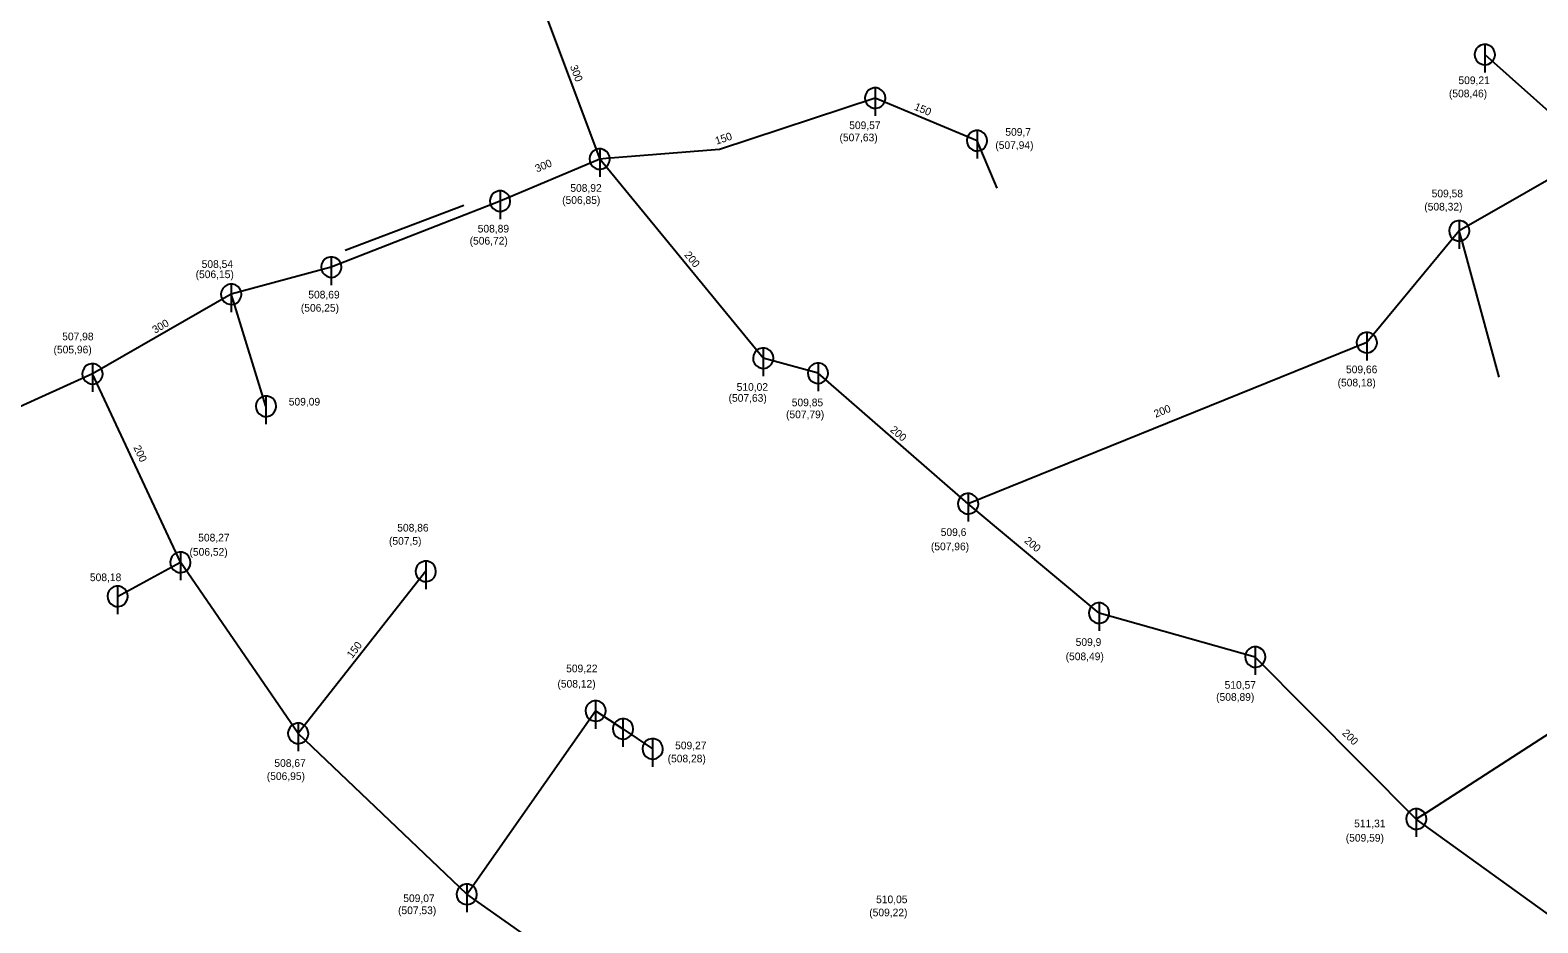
# Model space of a CAD drawing. Extents: x -476058 to -471893, y -1155786 to -1152000.
# Drawn here: x -475206.1 to -475058.6, y -1154304.2 to -1154216.9 of the extents above; entities that cross this region are included whole.
import ezdxf

# ---------------------------------------------------------------- set-up
doc = ezdxf.new("R2010")
doc.units = 0
for name, color, linetype in [('Vrstva 10', 7, 'Continuous'), ('Vrstva 18', 7, 'Continuous'), ('Vrstva 19', 7, 'Continuous'), ('Vrstva 23', 7, 'Continuous'), ('Vrstva 3', 7, 'Continuous'), ('Vrstva 4', 7, 'Continuous'), ('Vrstva 45', 7, 'Continuous'), ('Vrstva 50', 7, 'Continuous'), ('Vrstva 51', 7, 'Continuous')]:
    doc.layers.add(name, color=color, linetype=linetype)

msp = doc.modelspace()

# ---------------------------------------------------------------- linework, layer by layer
at = {"layer": 'Vrstva 10'}
for p, q in [((-475063.81, -1154218.28), (-475063.81, -1154221.03)), ((-475123.44, -1154222.53), (-475123.44, -1154225.28)), ((-475113.48, -1154226.71), (-475113.48, -1154229.46)), ((-475150.39, -1154228.5), (-475150.39, -1154231.25)), ((-475160.13, -1154232.61), (-475160.13, -1154235.36)), ((-475066.31, -1154235.52), (-475066.31, -1154238.27)), ((-475176.64, -1154239.07), (-475176.64, -1154241.82)), ((-475186.43, -1154241.72), (-475186.43, -1154244.47)), ((-475075.35, -1154246.44), (-475075.35, -1154249.19)), ((-475134.39, -1154247.97), (-475134.39, -1154250.72)), ((-475200, -1154249.5), (-475200, -1154252.25)), ((-475129.03, -1154249.44), (-475129.03, -1154252.19)), ((-475183.03, -1154252.67), (-475183.03, -1154255.42)), ((-475114.35, -1154262.2), (-475114.35, -1154264.95)), ((-475191.4, -1154267.93), (-475191.4, -1154270.68)), ((-475167.4, -1154268.81), (-475167.4, -1154271.56)), ((-475197.54, -1154271.26), (-475197.54, -1154274.01)), ((-475101.54, -1154272.89), (-475101.54, -1154275.64)), ((-475086.26, -1154277.19), (-475086.26, -1154279.94)), ((-475150.79, -1154282.46), (-475150.79, -1154285.21)), ((-475148.11, -1154284.22), (-475148.11, -1154286.96)), ((-475179.88, -1154284.66), (-475179.88, -1154287.41)), ((-475145.21, -1154286.17), (-475145.21, -1154288.92)), ((-475070.51, -1154293.03), (-475070.51, -1154295.78)), ((-475163.39, -1154300.39), (-475163.39, -1154303.14))]:
    msp.add_line(p, q, dxfattribs=at)
for points in [[(-475062.81, -1154219.28), (-475062.85, -1154219), (-475062.97, -1154218.74), (-475063.15, -1154218.53), (-475063.39, -1154218.38), (-475063.66, -1154218.29), (-475063.94, -1154218.29), (-475064.21, -1154218.36), (-475064.45, -1154218.51), (-475064.64, -1154218.72), (-475064.76, -1154218.97), (-475064.81, -1154219.25), (-475064.78, -1154219.53), (-475064.67, -1154219.79), (-475064.49, -1154220.01), (-475064.26, -1154220.17), (-475063.99, -1154220.26), (-475063.71, -1154220.28), (-475063.44, -1154220.21), (-475063.19, -1154220.07), (-475063, -1154219.86), (-475062.87, -1154219.61), (-475062.81, -1154219.34), (-475062.81, -1154219.28)], [(-475122.44, -1154223.53), (-475122.48, -1154223.25), (-475122.59, -1154223), (-475122.78, -1154222.78), (-475123.01, -1154222.63), (-475123.28, -1154222.54), (-475123.56, -1154222.54), (-475123.84, -1154222.62), (-475124.08, -1154222.76), (-475124.27, -1154222.97), (-475124.39, -1154223.23), (-475124.44, -1154223.51), (-475124.41, -1154223.79), (-475124.3, -1154224.05), (-475124.12, -1154224.27), (-475123.89, -1154224.43), (-475123.62, -1154224.52), (-475123.34, -1154224.53), (-475123.06, -1154224.46), (-475122.82, -1154224.32), (-475122.62, -1154224.12), (-475122.49, -1154223.87), (-475122.44, -1154223.59), (-475122.44, -1154223.53)], [(-475112.48, -1154227.71), (-475112.52, -1154227.43), (-475112.64, -1154227.17), (-475112.82, -1154226.96), (-475113.05, -1154226.8), (-475113.33, -1154226.72), (-475113.61, -1154226.72), (-475113.88, -1154226.79), (-475114.12, -1154226.94), (-475114.31, -1154227.15), (-475114.43, -1154227.4), (-475114.48, -1154227.68), (-475114.45, -1154227.96), (-475114.34, -1154228.22), (-475114.16, -1154228.44), (-475113.93, -1154228.6), (-475113.66, -1154228.69), (-475113.38, -1154228.71), (-475113.11, -1154228.64), (-475112.86, -1154228.5), (-475112.67, -1154228.29), (-475112.54, -1154228.04), (-475112.48, -1154227.77), (-475112.48, -1154227.71)], [(-475149.39, -1154229.5), (-475149.43, -1154229.22), (-475149.55, -1154228.96), (-475149.73, -1154228.75), (-475149.97, -1154228.59), (-475150.23, -1154228.51), (-475150.52, -1154228.51), (-475150.79, -1154228.58), (-475151.03, -1154228.73), (-475151.22, -1154228.94), (-475151.34, -1154229.19), (-475151.39, -1154229.47), (-475151.36, -1154229.75), (-475151.25, -1154230.01), (-475151.07, -1154230.23), (-475150.84, -1154230.39), (-475150.57, -1154230.48), (-475150.29, -1154230.5), (-475150.02, -1154230.43), (-475149.77, -1154230.29), (-475149.58, -1154230.08), (-475149.45, -1154229.83), (-475149.39, -1154229.56), (-475149.39, -1154229.5)], [(-475159.13, -1154233.61), (-475159.17, -1154233.33), (-475159.29, -1154233.07), (-475159.47, -1154232.86), (-475159.71, -1154232.71), (-475159.98, -1154232.62), (-475160.26, -1154232.62), (-475160.53, -1154232.69), (-475160.77, -1154232.84), (-475160.96, -1154233.05), (-475161.08, -1154233.3), (-475161.13, -1154233.58), (-475161.1, -1154233.86), (-475160.99, -1154234.12), (-475160.81, -1154234.34), (-475160.58, -1154234.5), (-475160.31, -1154234.59), (-475160.03, -1154234.61), (-475159.76, -1154234.54), (-475159.51, -1154234.4), (-475159.32, -1154234.19), (-475159.19, -1154233.94), (-475159.13, -1154233.67), (-475159.13, -1154233.61)], [(-475065.31, -1154236.52), (-475065.35, -1154236.24), (-475065.47, -1154235.98), (-475065.65, -1154235.77), (-475065.89, -1154235.61), (-475066.16, -1154235.53), (-475066.44, -1154235.53), (-475066.71, -1154235.6), (-475066.95, -1154235.75), (-475067.14, -1154235.96), (-475067.26, -1154236.21), (-475067.31, -1154236.49), (-475067.28, -1154236.77), (-475067.17, -1154237.03), (-475066.99, -1154237.25), (-475066.76, -1154237.41), (-475066.49, -1154237.5), (-475066.21, -1154237.52), (-475065.94, -1154237.45), (-475065.69, -1154237.31), (-475065.5, -1154237.1), (-475065.37, -1154236.85), (-475065.31, -1154236.58), (-475065.31, -1154236.52)], [(-475175.64, -1154240.07), (-475175.68, -1154239.79), (-475175.8, -1154239.53), (-475175.98, -1154239.32), (-475176.22, -1154239.17), (-475176.48, -1154239.08), (-475176.77, -1154239.08), (-475177.04, -1154239.15), (-475177.28, -1154239.3), (-475177.47, -1154239.51), (-475177.59, -1154239.76), (-475177.64, -1154240.04), (-475177.61, -1154240.32), (-475177.5, -1154240.58), (-475177.32, -1154240.8), (-475177.09, -1154240.96), (-475176.82, -1154241.05), (-475176.54, -1154241.07), (-475176.27, -1154241), (-475176.02, -1154240.86), (-475175.83, -1154240.65), (-475175.7, -1154240.4), (-475175.64, -1154240.13), (-475175.64, -1154240.07)], [(-475185.43, -1154242.72), (-475185.47, -1154242.44), (-475185.59, -1154242.18), (-475185.77, -1154241.97), (-475186.01, -1154241.81), (-475186.28, -1154241.73), (-475186.56, -1154241.73), (-475186.83, -1154241.8), (-475187.07, -1154241.95), (-475187.26, -1154242.16), (-475187.38, -1154242.41), (-475187.43, -1154242.69), (-475187.4, -1154242.97), (-475187.29, -1154243.23), (-475187.11, -1154243.45), (-475186.88, -1154243.61), (-475186.61, -1154243.7), (-475186.33, -1154243.72), (-475186.06, -1154243.65), (-475185.81, -1154243.51), (-475185.62, -1154243.3), (-475185.49, -1154243.05), (-475185.43, -1154242.78), (-475185.43, -1154242.72)], [(-475074.35, -1154247.44), (-475074.39, -1154247.16), (-475074.51, -1154246.9), (-475074.69, -1154246.69), (-475074.92, -1154246.53), (-475075.2, -1154246.45), (-475075.48, -1154246.45), (-475075.75, -1154246.52), (-475075.99, -1154246.67), (-475076.18, -1154246.88), (-475076.3, -1154247.13), (-475076.35, -1154247.41), (-475076.32, -1154247.69), (-475076.21, -1154247.95), (-475076.03, -1154248.17), (-475075.8, -1154248.33), (-475075.53, -1154248.42), (-475075.25, -1154248.44), (-475074.98, -1154248.37), (-475074.73, -1154248.23), (-475074.54, -1154248.02), (-475074.41, -1154247.77), (-475074.35, -1154247.5), (-475074.35, -1154247.44)], [(-475133.39, -1154248.97), (-475133.43, -1154248.69), (-475133.55, -1154248.43), (-475133.73, -1154248.22), (-475133.97, -1154248.06), (-475134.23, -1154247.98), (-475134.52, -1154247.98), (-475134.79, -1154248.05), (-475135.03, -1154248.2), (-475135.22, -1154248.41), (-475135.34, -1154248.66), (-475135.39, -1154248.94), (-475135.36, -1154249.22), (-475135.25, -1154249.48), (-475135.07, -1154249.7), (-475134.84, -1154249.86), (-475134.57, -1154249.95), (-475134.29, -1154249.97), (-475134.02, -1154249.9), (-475133.77, -1154249.76), (-475133.58, -1154249.55), (-475133.45, -1154249.3), (-475133.39, -1154249.03), (-475133.39, -1154248.97)], [(-475199, -1154250.5), (-475199.04, -1154250.22), (-475199.16, -1154249.96), (-475199.34, -1154249.75), (-475199.58, -1154249.59), (-475199.85, -1154249.51), (-475200.13, -1154249.51), (-475200.4, -1154249.58), (-475200.64, -1154249.73), (-475200.83, -1154249.94), (-475200.95, -1154250.19), (-475201, -1154250.47), (-475200.97, -1154250.75), (-475200.86, -1154251.01), (-475200.68, -1154251.23), (-475200.45, -1154251.39), (-475200.18, -1154251.48), (-475199.9, -1154251.5), (-475199.63, -1154251.43), (-475199.38, -1154251.29), (-475199.19, -1154251.08), (-475199.06, -1154250.83), (-475199, -1154250.56), (-475199, -1154250.5)], [(-475128.03, -1154250.44), (-475128.07, -1154250.16), (-475128.19, -1154249.9), (-475128.37, -1154249.69), (-475128.61, -1154249.53), (-475128.88, -1154249.45), (-475129.16, -1154249.45), (-475129.43, -1154249.52), (-475129.67, -1154249.67), (-475129.86, -1154249.88), (-475129.98, -1154250.13), (-475130.03, -1154250.41), (-475130, -1154250.69), (-475129.89, -1154250.95), (-475129.71, -1154251.17), (-475129.48, -1154251.33), (-475129.22, -1154251.42), (-475128.93, -1154251.44), (-475128.66, -1154251.37), (-475128.42, -1154251.23), (-475128.22, -1154251.02), (-475128.09, -1154250.77), (-475128.03, -1154250.5), (-475128.03, -1154250.44)], [(-475182.03, -1154253.67), (-475182.07, -1154253.39), (-475182.18, -1154253.14), (-475182.37, -1154252.92), (-475182.6, -1154252.77), (-475182.87, -1154252.69), (-475183.16, -1154252.68), (-475183.43, -1154252.76), (-475183.67, -1154252.9), (-475183.86, -1154253.11), (-475183.98, -1154253.37), (-475184.03, -1154253.65), (-475184, -1154253.93), (-475183.89, -1154254.19), (-475183.71, -1154254.41), (-475183.48, -1154254.57), (-475183.21, -1154254.66), (-475182.93, -1154254.67), (-475182.66, -1154254.6), (-475182.41, -1154254.46), (-475182.22, -1154254.26), (-475182.09, -1154254.01), (-475182.03, -1154253.73), (-475182.03, -1154253.67)], [(-475113.35, -1154263.2), (-475113.39, -1154262.92), (-475113.51, -1154262.66), (-475113.69, -1154262.45), (-475113.92, -1154262.29), (-475114.2, -1154262.21), (-475114.48, -1154262.21), (-475114.75, -1154262.28), (-475114.99, -1154262.43), (-475115.18, -1154262.64), (-475115.3, -1154262.89), (-475115.35, -1154263.17), (-475115.32, -1154263.45), (-475115.21, -1154263.71), (-475115.03, -1154263.93), (-475114.8, -1154264.09), (-475114.53, -1154264.18), (-475114.25, -1154264.2), (-475113.98, -1154264.13), (-475113.73, -1154263.99), (-475113.54, -1154263.78), (-475113.41, -1154263.53), (-475113.35, -1154263.26), (-475113.35, -1154263.2)], [(-475190.4, -1154268.93), (-475190.44, -1154268.65), (-475190.56, -1154268.39), (-475190.74, -1154268.18), (-475190.98, -1154268.03), (-475191.24, -1154267.94), (-475191.53, -1154267.94), (-475191.8, -1154268.01), (-475192.04, -1154268.16), (-475192.23, -1154268.37), (-475192.35, -1154268.62), (-475192.4, -1154268.9), (-475192.37, -1154269.18), (-475192.26, -1154269.44), (-475192.08, -1154269.66), (-475191.85, -1154269.82), (-475191.58, -1154269.91), (-475191.3, -1154269.93), (-475191.03, -1154269.86), (-475190.78, -1154269.72), (-475190.59, -1154269.51), (-475190.46, -1154269.26), (-475190.4, -1154268.99), (-475190.4, -1154268.93)], [(-475166.4, -1154269.81), (-475166.44, -1154269.53), (-475166.55, -1154269.28), (-475166.74, -1154269.06), (-475166.97, -1154268.91), (-475167.24, -1154268.83), (-475167.53, -1154268.82), (-475167.8, -1154268.9), (-475168.04, -1154269.04), (-475168.23, -1154269.25), (-475168.35, -1154269.51), (-475168.4, -1154269.79), (-475168.37, -1154270.07), (-475168.26, -1154270.33), (-475168.08, -1154270.55), (-475167.85, -1154270.71), (-475167.58, -1154270.8), (-475167.3, -1154270.81), (-475167.02, -1154270.74), (-475166.78, -1154270.6), (-475166.59, -1154270.4), (-475166.46, -1154270.15), (-475166.4, -1154269.87), (-475166.4, -1154269.81)], [(-475196.54, -1154272.26), (-475196.58, -1154271.98), (-475196.7, -1154271.72), (-475196.88, -1154271.51), (-475197.11, -1154271.35), (-475197.39, -1154271.27), (-475197.67, -1154271.27), (-475197.94, -1154271.34), (-475198.18, -1154271.49), (-475198.37, -1154271.7), (-475198.49, -1154271.95), (-475198.54, -1154272.23), (-475198.51, -1154272.51), (-475198.4, -1154272.77), (-475198.22, -1154272.99), (-475197.99, -1154273.15), (-475197.72, -1154273.24), (-475197.44, -1154273.26), (-475197.17, -1154273.19), (-475196.92, -1154273.05), (-475196.73, -1154272.84), (-475196.6, -1154272.59), (-475196.54, -1154272.32), (-475196.54, -1154272.26)], [(-475100.54, -1154273.89), (-475100.58, -1154273.61), (-475100.7, -1154273.35), (-475100.88, -1154273.14), (-475101.11, -1154272.99), (-475101.39, -1154272.9), (-475101.67, -1154272.9), (-475101.94, -1154272.97), (-475102.18, -1154273.12), (-475102.37, -1154273.33), (-475102.49, -1154273.58), (-475102.54, -1154273.86), (-475102.51, -1154274.14), (-475102.4, -1154274.4), (-475102.22, -1154274.62), (-475101.99, -1154274.78), (-475101.72, -1154274.87), (-475101.44, -1154274.89), (-475101.17, -1154274.82), (-475100.92, -1154274.68), (-475100.73, -1154274.47), (-475100.6, -1154274.22), (-475100.54, -1154273.95), (-475100.54, -1154273.89)], [(-475085.26, -1154278.19), (-475085.3, -1154277.91), (-475085.42, -1154277.65), (-475085.6, -1154277.44), (-475085.84, -1154277.28), (-475086.1, -1154277.2), (-475086.39, -1154277.2), (-475086.66, -1154277.27), (-475086.9, -1154277.42), (-475087.09, -1154277.63), (-475087.21, -1154277.88), (-475087.26, -1154278.16), (-475087.23, -1154278.44), (-475087.12, -1154278.7), (-475086.94, -1154278.92), (-475086.71, -1154279.08), (-475086.44, -1154279.17), (-475086.16, -1154279.19), (-475085.89, -1154279.12), (-475085.64, -1154278.98), (-475085.45, -1154278.77), (-475085.32, -1154278.52), (-475085.26, -1154278.25), (-475085.26, -1154278.19)], [(-475149.79, -1154283.46), (-475149.83, -1154283.18), (-475149.95, -1154282.92), (-475150.13, -1154282.71), (-475150.36, -1154282.55), (-475150.64, -1154282.47), (-475150.92, -1154282.47), (-475151.19, -1154282.54), (-475151.43, -1154282.69), (-475151.62, -1154282.9), (-475151.74, -1154283.15), (-475151.79, -1154283.43), (-475151.76, -1154283.71), (-475151.65, -1154283.97), (-475151.47, -1154284.19), (-475151.24, -1154284.35), (-475150.97, -1154284.44), (-475150.69, -1154284.46), (-475150.42, -1154284.39), (-475150.17, -1154284.25), (-475149.98, -1154284.04), (-475149.85, -1154283.79), (-475149.79, -1154283.52), (-475149.79, -1154283.46)], [(-475147.11, -1154285.22), (-475147.15, -1154284.94), (-475147.26, -1154284.68), (-475147.45, -1154284.46), (-475147.68, -1154284.31), (-475147.95, -1154284.23), (-475148.23, -1154284.22), (-475148.51, -1154284.3), (-475148.75, -1154284.45), (-475148.94, -1154284.66), (-475149.06, -1154284.91), (-475149.11, -1154285.19), (-475149.08, -1154285.47), (-475148.97, -1154285.73), (-475148.79, -1154285.95), (-475148.56, -1154286.11), (-475148.29, -1154286.2), (-475148.01, -1154286.21), (-475147.73, -1154286.14), (-475147.49, -1154286), (-475147.29, -1154285.8), (-475147.16, -1154285.55), (-475147.11, -1154285.27), (-475147.11, -1154285.22)], [(-475178.88, -1154285.66), (-475178.92, -1154285.38), (-475179.04, -1154285.12), (-475179.22, -1154284.91), (-475179.46, -1154284.76), (-475179.73, -1154284.67), (-475180.01, -1154284.67), (-475180.28, -1154284.74), (-475180.52, -1154284.89), (-475180.71, -1154285.1), (-475180.83, -1154285.35), (-475180.88, -1154285.63), (-475180.85, -1154285.91), (-475180.74, -1154286.17), (-475180.56, -1154286.39), (-475180.33, -1154286.55), (-475180.06, -1154286.64), (-475179.78, -1154286.66), (-475179.51, -1154286.59), (-475179.26, -1154286.45), (-475179.07, -1154286.24), (-475178.94, -1154285.99), (-475178.88, -1154285.72), (-475178.88, -1154285.66)], [(-475144.21, -1154287.17), (-475144.24, -1154286.89), (-475144.36, -1154286.64), (-475144.54, -1154286.42), (-475144.78, -1154286.27), (-475145.05, -1154286.18), (-475145.33, -1154286.18), (-475145.6, -1154286.26), (-475145.84, -1154286.4), (-475146.03, -1154286.61), (-475146.16, -1154286.87), (-475146.21, -1154287.14), (-475146.17, -1154287.43), (-475146.06, -1154287.69), (-475145.89, -1154287.9), (-475145.66, -1154288.07), (-475145.39, -1154288.16), (-475145.1, -1154288.17), (-475144.83, -1154288.1), (-475144.59, -1154287.96), (-475144.39, -1154287.76), (-475144.26, -1154287.51), (-475144.21, -1154287.23), (-475144.21, -1154287.17)], [(-475069.51, -1154294.03), (-475069.55, -1154293.75), (-475069.67, -1154293.49), (-475069.85, -1154293.28), (-475070.09, -1154293.12), (-475070.35, -1154293.04), (-475070.64, -1154293.04), (-475070.91, -1154293.11), (-475071.15, -1154293.26), (-475071.34, -1154293.47), (-475071.46, -1154293.72), (-475071.51, -1154294), (-475071.48, -1154294.28), (-475071.37, -1154294.54), (-475071.19, -1154294.76), (-475070.96, -1154294.92), (-475070.69, -1154295.01), (-475070.41, -1154295.03), (-475070.14, -1154294.96), (-475069.89, -1154294.82), (-475069.7, -1154294.61), (-475069.57, -1154294.36), (-475069.51, -1154294.09), (-475069.51, -1154294.03)], [(-475162.39, -1154301.39), (-475162.43, -1154301.11), (-475162.55, -1154300.85), (-475162.73, -1154300.64), (-475162.97, -1154300.49), (-475163.23, -1154300.4), (-475163.52, -1154300.4), (-475163.79, -1154300.47), (-475164.03, -1154300.62), (-475164.22, -1154300.83), (-475164.34, -1154301.08), (-475164.39, -1154301.36), (-475164.36, -1154301.64), (-475164.25, -1154301.9), (-475164.07, -1154302.12), (-475163.84, -1154302.28), (-475163.57, -1154302.37), (-475163.29, -1154302.39), (-475163.02, -1154302.32), (-475162.77, -1154302.18), (-475162.58, -1154301.97), (-475162.45, -1154301.72), (-475162.39, -1154301.45), (-475162.39, -1154301.39)]]:
    msp.add_lwpolyline(points, dxfattribs=at)
at = {"layer": 'Vrstva 23'}
msp.add_lwpolyline([(-475175.28, -1154238.41), (-475163.67, -1154234.02)], dxfattribs=at)
at = {"layer": 'Vrstva 45'}
for points in [[(-475156.26, -1154213.76), (-475150.39, -1154229.5)], [(-475150.39, -1154229.5), (-475160.13, -1154233.61)], [(-475134.39, -1154248.97), (-475150.39, -1154229.5)], [(-475052.97, -1154228.9), (-475066.31, -1154236.52)], [(-475160.13, -1154233.61), (-475176.64, -1154240.07)], [(-475066.31, -1154236.52), (-475075.35, -1154247.44)], [(-475176.64, -1154240.07), (-475186.43, -1154242.72)], [(-475186.43, -1154242.72), (-475200, -1154250.5)], [(-475075.35, -1154247.44), (-475114.35, -1154263.2)], [(-475129.03, -1154250.44), (-475134.39, -1154248.97)], [(-475200, -1154250.5), (-475222.79, -1154260.83)], [(-475191.4, -1154268.93), (-475200, -1154250.5)], [(-475114.35, -1154263.2), (-475129.03, -1154250.44)], [(-475101.54, -1154273.89), (-475114.35, -1154263.2)], [(-475179.88, -1154285.66), (-475191.4, -1154268.93)], [(-475086.26, -1154278.19), (-475101.54, -1154273.89)], [(-475070.51, -1154294.03), (-475086.26, -1154278.19)], [(-475163.39, -1154301.39), (-475179.88, -1154285.66)], [(-475018.84, -1154331.26), (-475070.51, -1154294.03)], [(-475140.01, -1154317.85), (-475163.39, -1154301.39)]]:
    msp.add_lwpolyline(points, dxfattribs=at)
at = {"layer": 'Vrstva 50'}
msp.add_line((-475069.56, -1154293.42), (-475051.06, -1154281.47), dxfattribs=at)
for points in [[(-475063.81, -1154219.28), (-475053.98, -1154228), (-475052.97, -1154228.9)], [(-475123.44, -1154223.53), (-475138.68, -1154228.57), (-475149.76, -1154229.45)], [(-475111.52, -1154232.34), (-475113.48, -1154227.71), (-475123.44, -1154223.53)], [(-475149.76, -1154229.45), (-475150.39, -1154229.5)], [(-475183.03, -1154253.67), (-475186.22, -1154243.41), (-475186.43, -1154242.72)], [(-475197.54, -1154272.26), (-475192.53, -1154269.54), (-475191.4, -1154268.93)], [(-475167.4, -1154269.81), (-475179.43, -1154285.09), (-475179.88, -1154285.66)], [(-475163.03, -1154300.88), (-475150.79, -1154283.46)], [(-475150.79, -1154283.46), (-475148.11, -1154285.22)], [(-475148.11, -1154285.22), (-475145.21, -1154287.17)], [(-475069.56, -1154293.42), (-475070.51, -1154294.03)], [(-475163.39, -1154301.39), (-475163.03, -1154300.88)]]:
    msp.add_lwpolyline(points, dxfattribs=at)
at = {"layer": 'Vrstva 51'}
msp.add_lwpolyline([(-475062.39, -1154250.83), (-475065.97, -1154237.75), (-475066.31, -1154236.52)], dxfattribs=at)

# ---------------------------------------------------------------- texts
at = {"layer": 'Vrstva 18'}
for s, rotation, p in [('300 ', 290.8017, (-475153.31, -1154220.45)), ('300 ', 22.8783, (-475156.52, -1154230.82)), ('200 ', 309.4126, (-475142.16, -1154238.89)), ('300 ', 29.8267, (-475193.89, -1154246.59)), ('200 ', 22.0038, (-475096, -1154254.8)), ('200 ', 319.1362, (-475122.04, -1154256.07)), ('200 ', 295.0152, (-475196.02, -1154257.69)), ('200 ', 320.1549, (-475108.92, -1154266.92)), ('200 ', 314.8368, (-475077.82, -1154285.69))]:
    msp.add_text(s, height=0.75, rotation=rotation, dxfattribs=at).set_placement(p)
at = {"layer": 'Vrstva 19'}
for rotation, p in [(337.2147, (-475119.69, -1154224.65)), (18.6007, (-475138.95, -1154228.1)), (52.9024, (-475174.59, -1154278.38))]:
    msp.add_text('150 ', height=0.75, rotation=rotation, dxfattribs=at).set_placement(p)
at = {"layer": 'Vrstva 3'}
for s, p in [('509,21', (-475066.39, -1154222.17)), ('509,57', (-475125.98, -1154226.57)), ('509,7', (-475110.71, -1154227.22)), ('508,92', (-475153.26, -1154232.7)), ('509,58', (-475069.01, -1154233.24)), ('508,89', (-475162.32, -1154236.68)), ('508,54', (-475189.32, -1154240.14)), ('508,69', (-475178.89, -1154243.13)), ('507,98', (-475202.96, -1154247.22)), ('509,66', (-475077.39, -1154250.44)), ('510,02', (-475136.99, -1154252.16)), ('509,09', (-475180.8, -1154253.6)), ('509,85', (-475131.6, -1154253.67)), ('508,86', (-475170.19, -1154265.92)), ('508,27', (-475189.66, -1154266.89)), ('509,6', (-475117.03, -1154266.35)), ('508,18', (-475200.25, -1154270.77)), ('509,9', (-475103.83, -1154277.1)), ('509,22', (-475153.67, -1154279.68)), ('510,57', (-475089.26, -1154281.29)), ('509,27', (-475143.01, -1154287.21)), ('508,67', (-475182.21, -1154288.93)), ('511,31', (-475076.59, -1154294.84)), ('509,07', (-475169.6, -1154302.15)), ('510,05', (-475123.35, -1154302.26))]:
    msp.add_text(s, height=0.75, dxfattribs=at).set_placement(p)
at = {"layer": 'Vrstva 4'}
for s, p in [('(508,46)', (-475067.32, -1154223.46)), ('(507,63)', (-475126.93, -1154227.76)), ('(507,94)', (-475111.69, -1154228.51)), ('(506,85)', (-475154.06, -1154233.88)), ('(508,32)', (-475069.73, -1154234.53)), ('(506,72)', (-475163.11, -1154237.86)), ('(506,15)', (-475189.91, -1154241.14)), ('(506,25)', (-475179.62, -1154244.42)), ('(505,96)', (-475203.81, -1154248.5)), ('(508,18)', (-475078.21, -1154251.73)), ('(507,63)', (-475137.78, -1154253.23)), ('(507,79)', (-475132.16, -1154254.84)), ('(507,5)', (-475171, -1154267.21)), ('(506,52)', (-475190.51, -1154268.28)), ('(507,96)', (-475117.99, -1154267.75)), ('(508,49)', (-475104.81, -1154278.5)), ('(508,12)', (-475154.52, -1154281.18)), ('(508,89)', (-475090.09, -1154282.47)), ('(508,28)', (-475143.74, -1154288.49)), ('(506,95)', (-475182.95, -1154290.21)), ('(509,59)', (-475077.41, -1154296.24)), ('(507,53)', (-475170.11, -1154303.33)), ('(509,22)', (-475124.02, -1154303.54))]:
    msp.add_text(s, height=0.75, dxfattribs=at).set_placement(p)

doc.saveas('drawing.dxf')
